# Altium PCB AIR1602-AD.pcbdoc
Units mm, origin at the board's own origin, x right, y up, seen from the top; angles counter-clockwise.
Board outline 43.72 x 38.44 mm, 2 copper layers (Top Layer, Bottom Layer); 1 components, 0 nets, 86 pads, 0 vias.
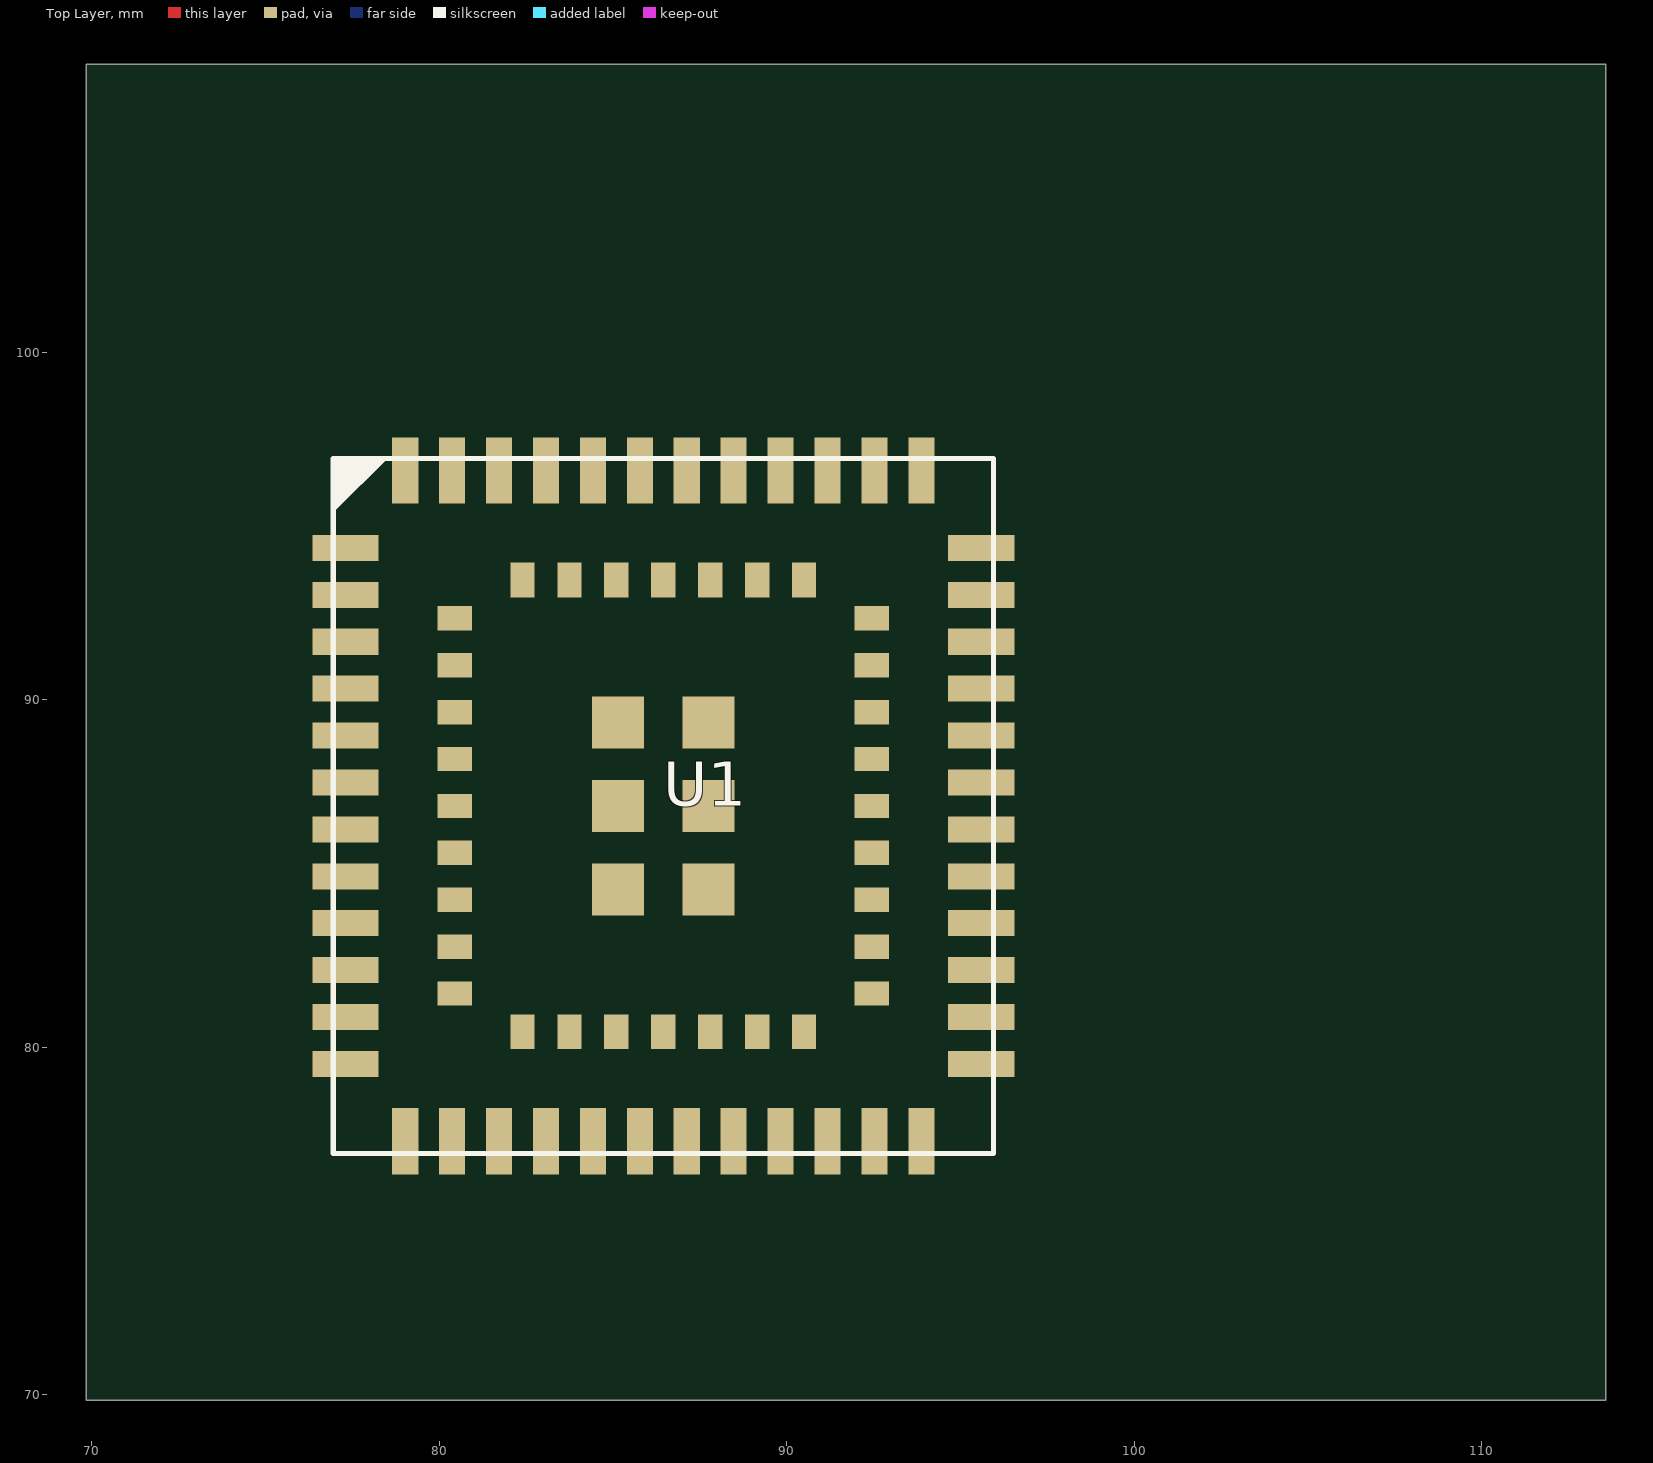
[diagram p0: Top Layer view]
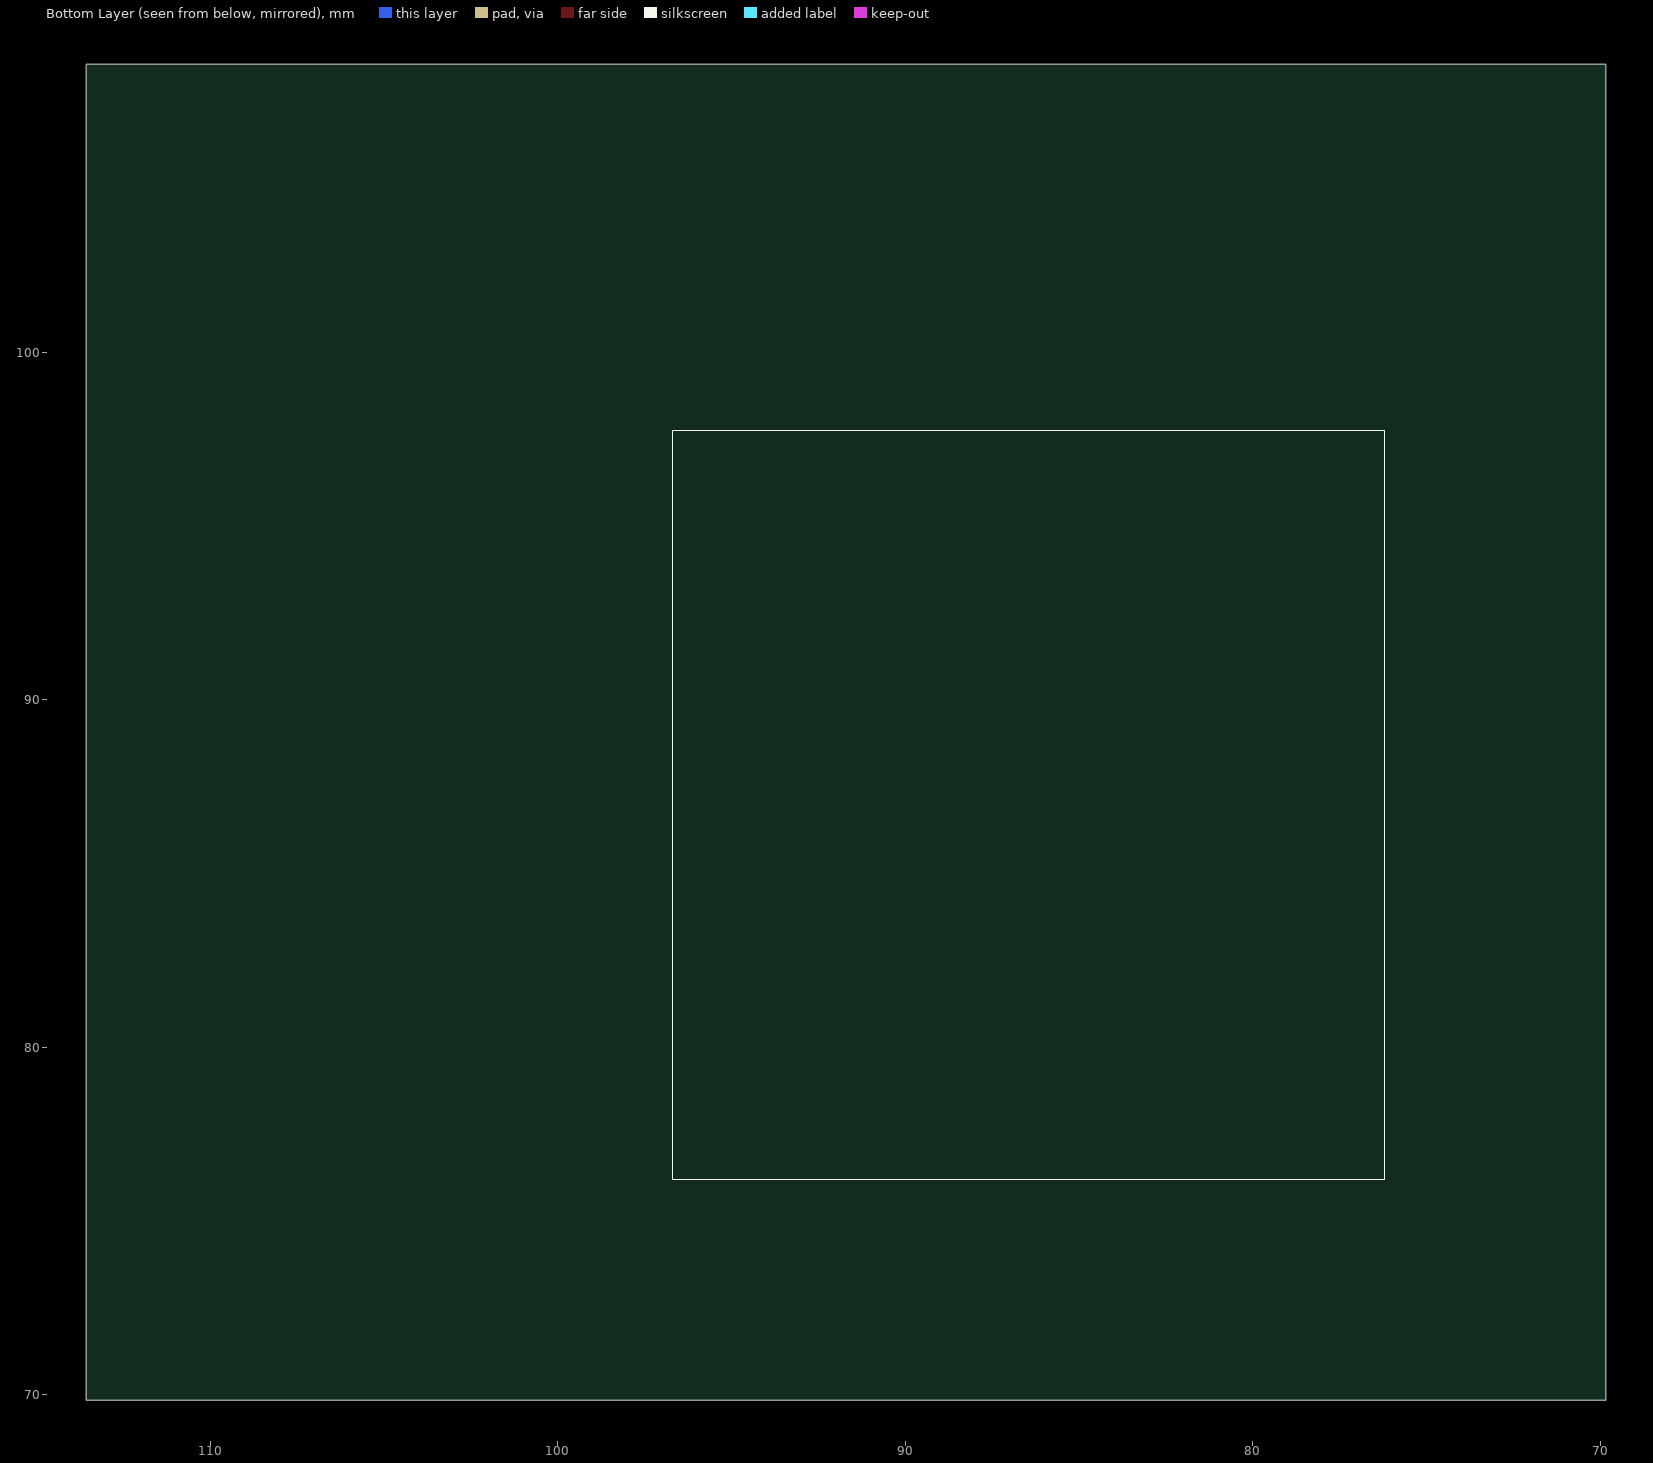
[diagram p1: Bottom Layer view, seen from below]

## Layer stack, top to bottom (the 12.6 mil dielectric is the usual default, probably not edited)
Top Layer: signal copper (thickness not stored)
Dielectric: dielectric 0.32, FR-4, Dk 4.8
Bottom Layer: signal copper (thickness not stored)

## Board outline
113.566,69.85 69.85,69.85 69.85,108.287 113.566,108.287

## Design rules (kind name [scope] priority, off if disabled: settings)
BoardOutlineClearance safeClearance [All] p0: genericclearance=0.254 ignorepadtopadclearanceinfootprint=FALSE except(0: Region-OutlineEdge Poly-OutlineEdge Text-OutlineEdge Sheet-OutlineEdge Hole-OutlineEdge Track-CutoutEdge SMDPad-CutoutEdge THPad-CutoutEdge Via-CutoutEdge Fill-CutoutEdge Region-CutoutEdge Poly-CutoutEdge Text-CutoutEdge Sheet-CutoutEdge Hole-CutoutEdge Arc-SplitContinuation Track-SplitContinuation SMDPad-SplitContinuation THPad-SplitContinuation Via-SplitContinuation Fill-SplitContinuation Poly-SplitContinuation Region-SplitContinuation Text-SplitContinuation; 0.152: Track-OutlineEdge SMDPad-OutlineEdge THPad-OutlineEdge Via-OutlineEdge Fill-OutlineEdge)
Clearance safeClearance [All] p1: gap=0.178 ignorepadtopadclearanceinfootprint=FALSE except(0: Region-Track Poly-Track Region-SMDPad Poly-SMDPad Region-THPad Poly-THPad Region-Via Poly-Via Region-Fill Poly-Fill Text-Fill Track-Region SMDPad-Region THPad-Region Via-Region Fill-Region Region-Region Poly-Region Text-Region Sheet-Region Hole-Region Track-Poly SMDPad-Poly THPad-Poly Via-Poly Fill-Poly Region-Poly Poly-Poly Text-Poly Sheet-Poly Hole-Poly Fill-Text Region-Text Poly-Text Text-Text Sheet-Text Hole-Text Region-Sheet Poly-Sheet Text-Sheet Sheet-Sheet Hole-Sheet Region-Hole Poly-Hole Text-Hole Sheet-Hole; 0.152: Track-Track SMDPad-Track THPad-Track Via-Track Fill-Track Text-Track Sheet-Track Hole-Track Track-SMDPad SMDPad-SMDPad THPad-SMDPad Via-SMDPad Fill-SMDPad Text-SMDPad Sheet-SMDPad Hole-SMDPad Track-THPad SMDPad-THPad THPad-THPad Via-THPad Fill-THPad Text-THPad Sheet-THPad Hole-THPad Track-Via SMDPad-Via THPad-Via Via-Via Fill-Via Text-Via Sheet-Via Hole-Via Track-Fill SMDPad-Fill THPad-Fill Via-Fill Fill-Fill Sheet-Fill Hole-Fill Track-Text SMDPad-Text THPad-Text Via-Text Track-Sheet SMDPad-Sheet THPad-Sheet Via-Sheet Fill-Sheet Track-Hole SMDPad-Hole THPad-Hole Via-Hole Fill-Hole Hole-Hole)
PasteMaskExpansion Common [All] p1: expansion=0
SolderMaskExpansion Common [All] p1: useseparateexpansions=TRUE expansion=0 expansionbottom=0
Width trackWidth [All] p1: maxlimit=12 minlimit=12 preferedwidth=12

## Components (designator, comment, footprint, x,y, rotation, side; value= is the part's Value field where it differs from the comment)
U1 "AIR1602-PADS" AIR1602-PADS 86.45,86.95 r0 top

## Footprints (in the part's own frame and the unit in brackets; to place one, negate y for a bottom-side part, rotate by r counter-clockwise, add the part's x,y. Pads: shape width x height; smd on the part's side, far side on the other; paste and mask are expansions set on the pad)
AIR1602-PADS [mm]
  rect 1.9x0.75 smd: 1(-9.15,7.425) 2(-9.15,6.075) 3(-9.15,4.725) 4(-9.15,3.375) 5(-9.15,2.025) 6(-9.15,0.675) 7(-9.15,-0.675) 8(-9.15,-2.025) 9(-9.15,-3.375) 10(-9.15,-4.725) 11(-9.15,-6.075) 12(-9.15,-7.425) 25(9.15,-7.425) 26(9.15,-6.075) 27(9.15,-4.725) 28(9.15,-3.375) 29(9.15,-2.025) 30(9.15,-0.675) 31(9.15,0.675) 32(9.15,2.025) 33(9.15,3.375) 34(9.15,4.725) 35(9.15,6.075) 36(9.15,7.425)
  rect 0.75x1.9 smd: 13(-7.425,-9.65) 14(-6.075,-9.65) 15(-4.725,-9.65) 16(-3.375,-9.65) 17(-2.025,-9.65) 18(-0.675,-9.65) 19(0.675,-9.65) 20(2.025,-9.65) 21(3.375,-9.65) 22(4.725,-9.65) 23(6.075,-9.65) 24(7.425,-9.65) 37(7.425,9.65) 38(6.075,9.65) 39(4.725,9.65) 40(3.375,9.65) 41(2.025,9.65) 42(0.675,9.65) 43(-0.675,9.65) 44(-2.025,9.65) 45(-3.375,9.65) 46(-4.725,9.65) 47(-6.075,9.65) 48(-7.425,9.65)
  rect 1x0.7 smd: 49(-6,5.4) 50(-6,4.05) 51(-6,2.7) 52(-6,1.35) 53(-6,0) 54(-6,-1.35) 55(-6,-2.7) 56(-6,-4.05) 57(-6,-5.4) 65(6,-5.4) 66(6,-4.05) 67(6,-2.7) 68(6,-1.35) 69(6,0) 70(6,1.35) 71(6,2.7) 72(6,4.05) 73(6,5.4)
  rect 0.7x1 smd: 58(-4.05,-6.5) 59(-2.7,-6.5) 60(-1.35,-6.5) 61(0,-6.5) 62(1.35,-6.5) 63(2.7,-6.5) 64(4.05,-6.5) 74(4.05,6.5) 75(2.7,6.5) 76(1.35,6.5) 77(0,6.5) 78(-1.35,6.5) 79(-2.7,6.5) 80(-4.05,6.5)
  rect 1.5x1.5 smd: 81(-1.3,2.4) 82(-1.3,0) 83(-1.3,-2.4) 84(1.3,-2.4) 85(1.3,0) 86(1.3,2.4)
  silkscreen extent -9.51,-10 9.5,10.05

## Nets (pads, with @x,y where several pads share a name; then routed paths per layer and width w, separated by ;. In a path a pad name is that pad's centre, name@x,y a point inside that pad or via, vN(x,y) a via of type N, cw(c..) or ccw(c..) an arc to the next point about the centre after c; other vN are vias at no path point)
pads on no net: U1.1 U1.2 U1.3 U1.4 U1.5 U1.6 U1.7 U1.8 U1.9 U1.10 U1.11 U1.12 U1.13 U1.14 U1.15 U1.16 U1.17 U1.18 U1.19 U1.20 U1.21 U1.22 U1.23 U1.24 U1.25 U1.26 U1.27 U1.28 U1.29 U1.30 U1.31 U1.32 U1.33 U1.34 U1.35 U1.36 U1.37 U1.38 U1.39 U1.40 U1.41 U1.42 U1.43 U1.44 U1.45 U1.46 U1.47 U1.48 U1.49 U1.50 U1.51 U1.52 U1.53 U1.54 U1.55 U1.56 U1.57 U1.58 U1.59 U1.60 U1.61 U1.62 U1.63 U1.64 U1.65 U1.66 U1.67 U1.68 U1.69 U1.70 U1.71 U1.72 U1.73 U1.74 U1.75 U1.76 U1.77 U1.78 U1.79 U1.80 U1.81 U1.82 U1.83 U1.84 U1.85 U1.86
